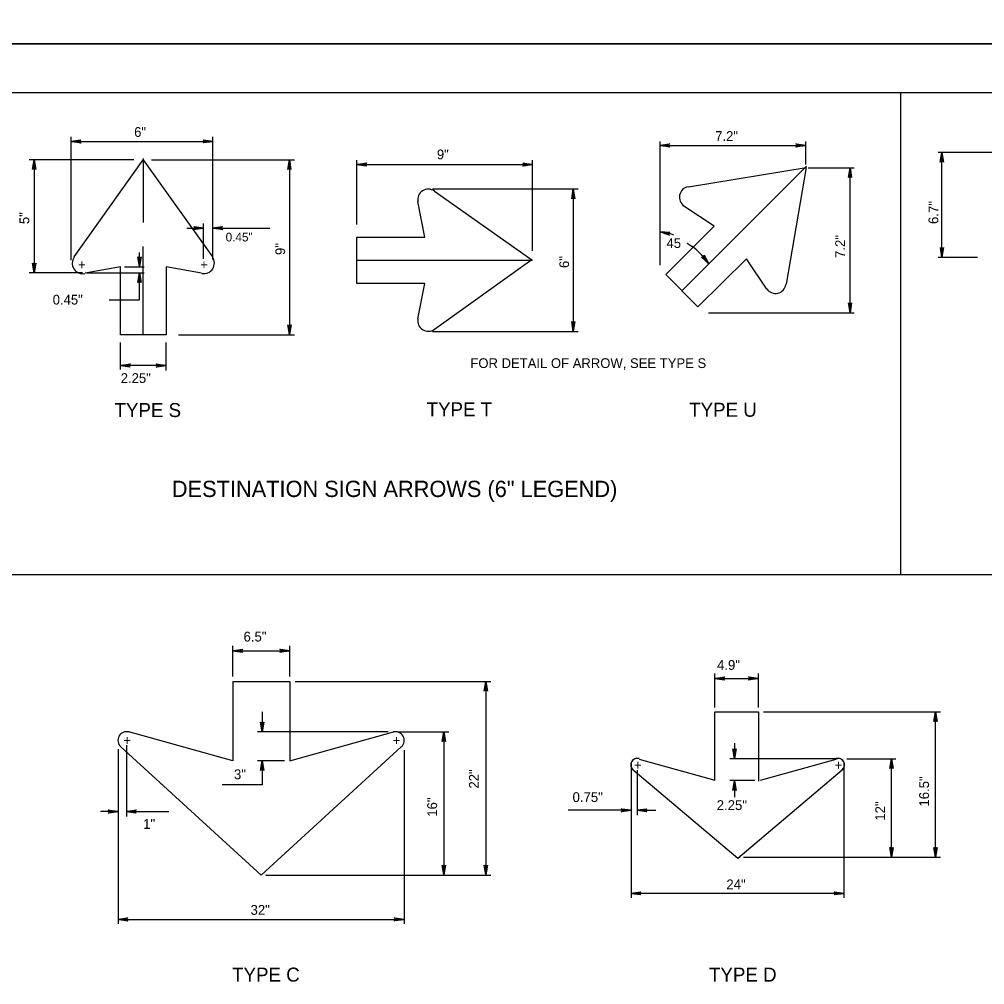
# Model space of a CAD drawing. Extents: x 638421 to 641849, y 297270 to 299646.
# Drawn here: x 641232.4 to 641528.9, y 298762.6 to 299059.1 of the extents above; entities that cross this region are included whole.
import ezdxf

# ---------------------------------------------------------------- set-up
doc = ezdxf.new("R2010")
doc.units = 0
for name, color, linetype in [('1', 7, 'Continuous'), ('2', 7, 'Continuous'), ('3', 7, 'Continuous'), ('XCS-GRID-HVGL', 7, 'Continuous')]:
    doc.layers.add(name, color=color, linetype=linetype)

# ---------------------------------------------------------------- blocks, each defined once
blk = doc.blocks.new('RARROW')
at = {"layer": '3'}
blk.add_lwpolyline([(-2.2695, 0.285), (-2.184875, 0.12075), (0, 0), (-2.2695, 0.285), (-2.38575, 0.384625), (0, 0), (-2.183125, -0.108), (-2.262875, -0.2705), (0, 0), (-2.38575, -0.379125), (-2.262875, -0.2705)], dxfattribs=at)

msp = doc.modelspace()

# ---------------------------------------------------------------- linework, layer by layer
at = {"layer": '1'}
msp.add_line((640984.31, 299036.63), (641770.31, 299036.63), dxfattribs=at)
for points in [[(641503.19, 298888.5), (641503.19, 299036.63)], [(641770.31, 298888.5), (640984.31, 298888.5)]]:
    msp.add_lwpolyline(points, dxfattribs=at)
at = {"layer": '2'}
for p, q in [((641248.31, 298985.13), (641248.31, 299023)), ((641291.81, 298985.38), (641291.81, 299023)), ((641248.31, 299021.63), (641291.81, 299021.63)), ((641429.19, 298983.63), (641429.19, 299021.63)), ((641429.19, 299020.38), (641473.94, 299020.38)), ((641473.94, 299014.5), (641473.94, 299021.63)), ((641267.56, 299016), (641235.44, 299016)), ((641236.94, 299016), (641236.94, 298981.25)), ((641249.19, 298986.13), (641270.44, 299016)), ((641270.44, 299016.38), (641270.44, 298996.75)), ((641270.44, 299016), (641270.44, 299016)), ((641270.44, 299016), (641291.69, 298986.13)), ((641272.94, 299016), (641316.94, 299016)), ((641315.33, 299016), (641315.33, 298962.25)), ((641549.69, 299018.25), (641514.69, 299018.25)), ((641515.81, 298986), (641515.81, 299018.25)), ((641336.06, 298996.13), (641336.06, 299015.88)), ((641336.06, 299014.5), (641390.06, 299014.5)), ((641390.06, 298988), (641390.06, 299015.88)), ((641435.94, 298975.75), (641474.19, 299014)), ((641437.94, 299007.63), (641474.06, 299013.63)), ((641474.06, 299013.63), (641467.94, 298977.75)), ((641474.69, 299013.5), (641488.81, 299013.5)), ((641487.56, 298969), (641487.56, 299013.5)), ((641359.31, 299007), (641404.06, 299007)), ((641402.56, 299007), (641402.56, 298963.25)), ((641359.94, 299006.38), (641389.81, 298985.25)), ((641356.94, 298992.25), (641354.81, 299003.13)), ((641445.81, 298995.63), (641436.56, 299001.75)), ((641288.94, 298985.5), (641288.94, 298996.38)), ((641430.94, 298980.75), (641445.81, 298995.63)), ((641283.81, 298995), (641288.94, 298995)), ((641291.81, 298995), (641309.32, 298995)), ((641336.06, 298978), (641336.06, 298992.25)), ((641336.06, 298992.25), (641356.94, 298992.25)), ((641270.44, 298962.25), (641270.44, 298989.38)), ((641269.31, 298983.13), (641269.31, 298987.5)), ((641336.06, 298985.13), (641390.06, 298985.13)), ((641389.81, 298985.25), (641359.94, 298963.88)), ((641455.81, 298985.5), (641440.81, 298970.75)), ((641462.06, 298976.25), (641455.81, 298985.5)), ((641526.69, 298986), (641514.69, 298986)), ((641251.81, 298981.25), (641235.44, 298981.25)), ((641263.44, 298983.13), (641252.56, 298981.13)), ((641253.06, 298981.25), (641270.69, 298981.25)), ((641263.44, 298983.13), (641263.44, 298983.13)), ((641263.44, 298962.25), (641263.44, 298983.13)), ((641264.69, 298983.13), (641270.69, 298983.13)), ((641269.31, 298973), (641269.31, 298981.25)), ((641277.44, 298983.13), (641277.44, 298983.13)), ((641288.31, 298981.13), (641277.44, 298983.13)), ((641277.44, 298983.13), (641277.44, 298962.25)), ((641440.81, 298970.75), (641430.94, 298980.75)), ((641356.94, 298978), (641336.06, 298978)), ((641354.81, 298967.13), (641356.94, 298978)), ((641259.94, 298973), (641269.31, 298973)), ((641444.06, 298969), (641488.81, 298969)), ((641359.31, 298963.25), (641404.06, 298963.25)), ((641263.44, 298962.25), (641263.44, 298962.25)), ((641277.44, 298962.25), (641263.44, 298962.25)), ((641263.44, 298951.5), (641263.44, 298959.88)), ((641277.44, 298962.25), (641277.44, 298962.25)), ((641277.44, 298951.25), (641277.44, 298959.88)), ((641281.31, 298962.25), (641316.94, 298962.25)), ((641277.44, 298952.75), (641263.44, 298952.75)), ((641297.94, 298857.25), (641297.94, 298866.63)), ((641297.94, 298865.13), (641315.44, 298865.13)), ((641315.44, 298857.25), (641315.44, 298866.63)), ((641297.94, 298855.75), (641297.94, 298855.75)), ((641297.94, 298855.75), (641297.94, 298831.38)), ((641297.94, 298855.75), (641315.44, 298855.75)), ((641315.44, 298855.75), (641315.44, 298855.75)), ((641315.44, 298855.75), (641315.44, 298831.38)), ((641317.06, 298855.75), (641377.19, 298855.75)), ((641375.69, 298855.75), (641375.69, 298796.25)), ((641446.04, 298856.63), (641459.42, 298856.63)), ((641446.06, 298847.75), (641446.06, 298858.13)), ((641459.44, 298847.75), (641459.44, 298858.13)), ((641306.94, 298846.38), (641306.94, 298840.25)), ((641446.06, 298846.38), (641446.06, 298846.38)), ((641446.06, 298825.38), (641446.06, 298846.38)), ((641446.06, 298846.38), (641459.44, 298846.38)), ((641459.44, 298846.38), (641459.44, 298846.38)), ((641459.44, 298846.38), (641459.44, 298825.13)), ((641460.94, 298846.38), (641515.31, 298846.38)), ((641513.81, 298801.75), (641513.81, 298846.38)), ((641263.44, 298839.63), (641263.44, 298839.63)), ((641297.94, 298831.38), (641266.06, 298840.25)), ((641345.69, 298840.25), (641305.56, 298840.25)), ((641315.44, 298831.38), (641347.31, 298840.25)), ((641348.69, 298840.25), (641364.31, 298840.25)), ((641349.81, 298839.63), (641349.81, 298839.63)), ((641362.81, 298840.25), (641362.81, 298796.25)), ((641306.69, 298796.25), (641263.56, 298835.63)), ((641265.31, 298836.13), (641265.31, 298814.25)), ((641306.69, 298796.25), (641349.69, 298835.63)), ((641452.06, 298836.75), (641452.06, 298832)), ((641262.69, 298834.88), (641262.69, 298781.25)), ((641262.69, 298834.63), (641262.69, 298814.25)), ((641350.56, 298834.63), (641350.56, 298781.25)), ((641297.94, 298831.38), (641297.94, 298831.38)), ((641313.81, 298831.38), (641305.56, 298831.38)), ((641306.69, 298831.38), (641306.69, 298831.38)), ((641306.69, 298831.38), (641306.69, 298831.38)), ((641306.94, 298831.38), (641306.94, 298823.96)), ((641315.44, 298831.38), (641315.44, 298831.38)), ((641420.31, 298832), (641420.31, 298832)), ((641420.31, 298830.63), (641420.31, 298814.63)), ((641420.31, 298830.63), (641420.31, 298789.25)), ((641422.81, 298831.88), (641446.06, 298825.38)), ((641483.69, 298832), (641450.69, 298832)), ((641460.06, 298825.38), (641483.31, 298831.88)), ((641485.06, 298832), (641485.06, 298832)), ((641485.69, 298832), (641485.69, 298832)), ((641485.69, 298830.63), (641485.69, 298789.25)), ((641486.56, 298832), (641501.69, 298832)), ((641500.31, 298801.75), (641500.31, 298832)), ((641453.06, 298801.38), (641420.94, 298828.5)), ((641422.19, 298828.5), (641422.19, 298814.63)), ((641485.19, 298828.5), (641453.06, 298801.38)), ((641306.94, 298823.96), (641294.64, 298823.96)), ((641446.31, 298825.25), (641446.31, 298825.25)), ((641458.31, 298825.25), (641450.69, 298825.25)), ((641452.06, 298825.25), (641452.06, 298820.13)), ((641453.06, 298825.25), (641453.06, 298825.25)), ((641459.69, 298825.25), (641459.69, 298825.25)), ((641262.69, 298815.75), (641257.31, 298815.75)), ((641265.31, 298815.75), (641278.31, 298815.75)), ((641420.31, 298816.13), (641400.94, 298816.13)), ((641422.19, 298816.13), (641427.94, 298816.13)), ((641452.81, 298801.75), (641452.81, 298801.75)), ((641452.81, 298801.75), (641452.81, 298801.75)), ((641454.81, 298801.75), (641501.69, 298801.75)), ((641454.81, 298801.75), (641515.31, 298801.75)), ((641306.69, 298796.25), (641306.69, 298796.25)), ((641306.69, 298796.25), (641306.69, 298796.25)), ((641308.06, 298796.25), (641377.19, 298796.25)), ((641308.06, 298796.25), (641364.31, 298796.25)), ((641485.69, 298790.63), (641420.31, 298790.63)), ((641262.69, 298782.63), (641350.56, 298782.63))]:
    msp.add_line(p, q, dxfattribs=at)
for centre, radius, start, end in [((641438.39, 299004.46), 3.24, 99.584, 235.9563), ((641358, 299003.71), 3.24, 54.5839, 190.9563), ((641427.08, 298975.31), 18.65, 70.1319, 83.4312), ((641428.5, 298973.89), 18.65, 32.7978, 61.1367), ((641251.86, 298984.22), 3.24, 144.584, 280.9563), ((641289.05, 298984.25), 3.24, 259.0428, 35.4161), ((641464.67, 298978.17), 3.24, 214.0428, 350.4161), ((641358, 298966.54), 3.24, 169.0428, 305.4161), ((641265.35, 298837.6), 2.7, 74.5414, 227.6502), ((641347.92, 298837.6), 2.7, 312.3498, 105.4586), ((641422.23, 298830.09), 2.02, 75.4325, 226.8476), ((641422.23, 298830.08), 2.02, 74.0715, 229.8431), ((641483.86, 298830.08), 2.02, 310.1569, 105.9285), ((641483.87, 298830.09), 2.02, 313.1524, 104.5675)]:
    msp.add_arc(centre, radius, start, end, dxfattribs=at)
at = {"layer": 'XCS-GRID-HVGL'}
for points in [[(640944.31, 299645.63), (641785.31, 299645.63), (641785.31, 299051.63), (640944.31, 299051.63)], [(640944.31, 299051.63), (641785.31, 299051.63), (641785.31, 298457.63), (640944.31, 298457.63)]]:
    msp.add_lwpolyline(points, close=True, dxfattribs=at)

# ---------------------------------------------------------------- block references
at = {"layer": '2', "xscale": 1.2574347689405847, "yscale": 1.3092961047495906}
for p, rotation in [((641248.31, 299021.63), 180), ((641429.19, 299020.38), 180), ((641236.94, 299016), 89.99999999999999), ((641315.33, 299016), 89.99999999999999), ((641515.81, 299018.25), 89.99999999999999), ((641336.06, 299014.5), 180), ((641487.56, 299013.5), 89.99999999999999), ((641402.56, 299007), 89.99999999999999), ((641291.81, 298995), 180), ((641429.21, 298993.83), 169.25034705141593), ((641444.18, 298983.99), -52.85020127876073), ((641515.81, 298986), -90.00000000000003), ((641236.94, 298981.25), -90.00000000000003), ((641269.31, 298983.13), -90.00000000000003), ((641269.31, 298981.25), 89.99999999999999), ((641487.56, 298969), -90.00000000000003), ((641402.56, 298963.25), -90.00000000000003), ((641315.33, 298962.25), -90.00000000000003), ((641263.44, 298952.75), 180), ((641297.94, 298865.13), 180), ((641375.69, 298855.75), 89.99999999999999), ((641446.04, 298856.63), 180), ((641513.81, 298846.38), 89.99999999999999), ((641306.94, 298840.25), -90.00000000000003), ((641362.81, 298840.25), 89.99999999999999), ((641452.06, 298832), -90.00000000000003), ((641306.94, 298831.38), 89.99999999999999), ((641500.31, 298832), 89.99999999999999), ((641452.06, 298825.25), 89.99999999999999), ((641265.31, 298815.75), 180), ((641422.19, 298816.13), 180), ((641500.31, 298801.75), -90.00000000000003), ((641513.81, 298801.75), -90.00000000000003), ((641362.81, 298796.25), -90.00000000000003), ((641375.69, 298796.25), -90.00000000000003), ((641420.31, 298790.63), 180), ((641262.69, 298782.63), 180)]:
    msp.add_blockref('RARROW', p, dxfattribs=dict(at, rotation=rotation))
for p in [(641291.81, 299021.63), (641473.94, 299020.38), (641390.06, 299014.5), (641288.94, 298995), (641277.44, 298952.75), (641315.44, 298865.13), (641459.42, 298856.63), (641262.69, 298815.75), (641420.31, 298816.13), (641485.69, 298790.63), (641350.56, 298782.63)]:
    msp.add_blockref('RARROW', p, dxfattribs=at)

# ---------------------------------------------------------------- texts
at = {"layer": '2'}
for s, height, p in [('6"', 3, (641267.65, 299023.01)), ('7.2"', 3, (641446.15, 299021.77)), ('9"', 3, (641360.65, 299016.12)), ('0.45"', 2.699, (641295.75, 298990.88)), ('45', 3, (641431.19, 298988.88)), ('+', 3, (641250.44, 298982.25)), ('+', 3, (641287.94, 298982.25)), (' 0.45"', 3, (641241.52, 298971.5)), ('FOR DETAIL OF ARROW, SEE TYPE S', 3, (641370.94, 298952)), ('2.25"', 3, (641263.53, 298947.42)), ('TYPE S', 4.3, (641261.61, 298936.94)), ('TYPE T', 4.3, (641357.49, 298937.17)), ('TYPE U', 4.3, (641438.15, 298937.02)), ('DESTINATION SIGN ARROWS (6" LEGEND)', 5, (641279.23, 298912.38)), ('6.5"', 3.022, (641301.25, 298867.99)), ('4.9"', 3.022, (641446.71, 298859.27)), ('+', 3.02, (641264.31, 298836.13)), ('+', 3.02, (641347.06, 298836.13)), ('+', 3.02, (641421.19, 298828.5)), ('+', 3.02, (641482.81, 298828.5)), ('3"', 3.022, (641298.31, 298825.69)), ('0.75"', 3.022, (641402.33, 298818.68)), ('2.25"', 3.022, (641446.61, 298816.22)), ('1"', 3.022, (641270.42, 298810.43)), ('24"', 3.022, (641449.57, 298791.86)), ('32"', 3.022, (641303.4, 298784.03)), ('TYPE C', 4.3, (641297.74, 298763.51)), ('TYPE D', 4.3, (641444.24, 298763.51))]:
    msp.add_text(s, height=height, dxfattribs=at).set_placement(p)
for s, height, p in [('6.7"', 3.022, (641514.7, 298996.24)), ('5"', 3, (641235.42, 298996.22)), ('7.2"', 3, (641486.01, 298985.84)), ('9"', 3, (641314.01, 298986.72)), ('6"', 3, (641401.26, 298982.72)), ('22"', 3.022, (641373.53, 298822.8)), ('16.5"', 3.022, (641511.84, 298817.28)), ('16"', 3.022, (641360.71, 298814.15)), ('12"', 3.022, (641498.35, 298812.93))]:
    msp.add_text(s, height=height, rotation=90, dxfattribs=at).set_placement(p)

doc.saveas('drawing.dxf')
